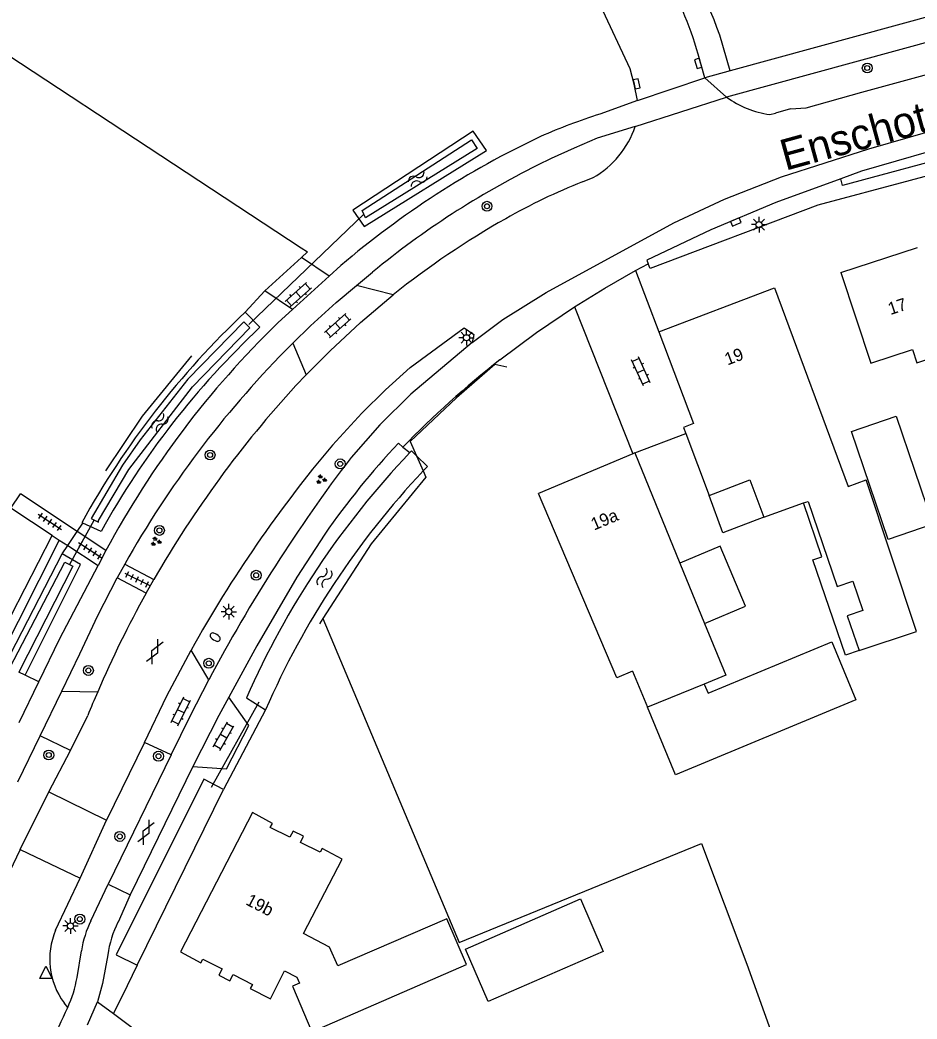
# Model space of a CAD drawing. Extents: x 136000 to 138005, y 398500 to 400500.
# Drawn here: x 137265.3 to 137337.6, y 398725.5 to 398806.1 of the extents above; entities that cross this region are included whole.
import ezdxf

# ---------------------------------------------------------------- set-up
doc = ezdxf.new("R2010")
doc.units = 0
for name, color, linetype in [('gg-afsc-erfafscheiding', 7, 'Continuous'), ('gg-afsc-hekwerk', 7, 'Continuous'), ('gg-anno-huisnummerreeks BGT', 7, 'Continuous'), ('gg-anno-openbare ruimte label', 7, 'Continuous'), ('gg-bbg-bijgebouw', 7, 'Continuous'), ('gg-bbg-gedigitaliseerde bebouwing', 7, 'Continuous'), ('gg-bbg-gedigitaliseerde bijgebouw', 7, 'Continuous'), ('gg-bbg-hoofdgebouw', 7, 'Continuous'), ('gg-bbg-luifel en loopbrug', 7, 'Continuous'), ('gg-bbg-tussenscheiding', 7, 'Continuous'), ('gg-knt-verharding', 7, 'Continuous'), ('gg-knt-verharding nz', 7, 'Continuous'), ('gg-kntw-bovenkant insteek waterloop', 7, 'Continuous'), ('gg-kntw-waterlijn', 7, 'Continuous'), ('gg-kwrk-duiker nz buis', 7, 'Continuous'), ('gt-grn-groengrens', 7, 'Continuous'), ('gt-grn-vlakafsluiter', 7, 'Continuous'), ('gt-grn-weggrens', 7, 'Continuous'), ('gt-grn-weggrens revisie', 7, 'Continuous'), ('gt-symb-boom', 7, 'Continuous'), ('gt-symb-brandkraan', 7, 'Continuous'), ('gt-symb-gesloten verharding', 7, 'Continuous'), ('gt-symb-groenvak', 7, 'Continuous'), ('gt-symb-klinker verharding', 7, 'Continuous'), ('gt-symb-kolk', 7, 'Continuous'), ('gt-symb-lichtmast', 7, 'Continuous'), ('gt-symb-tegel verharding', 7, 'Continuous'), ('gt-symb-waterafsluiter', 7, 'Continuous'), ('gt-symb-watersymbool', 7, 'Continuous')]:
    doc.layers.add(name, color=color, linetype=linetype)

# ---------------------------------------------------------------- blocks, each defined once
blk = doc.blocks.new('gt0-KOLK')
at = {"layer": 'gt-symb-kolk'}
blk.add_lwpolyline([(0, 0), (0.375, 0), (0.375, 0.4), (-0.375, 0.4), (-0.375, 0), (0, 0)], dxfattribs=at)
blk = doc.blocks.new('gt0-BOOM')
at = {"layer": 'gt-symb-boom'}
for radius in [0.4, 0.2]:
    blk.add_circle((0, 0), radius, dxfattribs=at)
blk = doc.blocks.new('gt0-LMAST')
at = {"layer": 'gt-symb-lichtmast'}
for p, q in [((-0.182, 0.173), (-0.447, 0.438)), ((-0.005, 0.246), (-0.005, 0.621)), ((0.172, 0.173), (0.437, 0.438)), ((-0.255, -0.004), (-0.63, -0.004)), ((-0.182, -0.181), (-0.447, -0.446)), ((-0.005, -0.254), (-0.005, -0.629)), ((0.437, -0.446), (0.172, -0.181)), ((0.245, -0.004), (0.62, -0.004))]:
    blk.add_line(p, q, dxfattribs=at)
blk.add_circle((-0.005, -0.004), 0.25, dxfattribs=at)
blk = doc.blocks.new('gt0-WA')
at = {"layer": 'gt-symb-watersymbool'}
for centre, start, end in [((-0.323, 0.022), 28.07249, 151.92751), ((0.427, 0.422), 208.07248, 331.92751), ((-0.323, -0.428), 28.07249, 151.92751), ((0.427, -0.028), 208.07248, 331.92751)]:
    blk.add_arc(centre, 0.425, start, end, dxfattribs=at)
blk = doc.blocks.new('gt0-KL1')
at = {"layer": 'gt-symb-klinker verharding'}
for p, q in [((-1.15, 0.3), (1.15, 0.3)), ((-1, -0.3), (-1, 0.3)), ((-0.5, 0.3), (-0.5, 0.45)), ((0, -0.3), (0, 0.3)), ((0.5, 0.3), (0.5, 0.45)), ((1, -0.3), (1, 0.3)), ((-1.15, -0.3), (1.15, -0.3)), ((-0.5, -0.45), (-0.5, -0.3)), ((0.5, -0.45), (0.5, -0.3))]:
    blk.add_line(p, q, dxfattribs=at)
blk = doc.blocks.new('gt0-GRVAK')
at = {"layer": 'gt-symb-groenvak'}
for p, q in [((-0.11, 0.189), (-0.228, 0.24)), ((-0.182, 0.153), (0.088, 0.153)), ((-0.091, 0.211), (-0.156, 0.322)), ((-0.047, 0.214), (-0.047, 0.393)), ((-0.004, 0.211), (0.061, 0.322)), ((0.015, 0.189), (0.133, 0.24)), ((0.262, -0.052), (0.197, 0.059)), ((0.305, -0.049), (0.305, 0.13)), ((0.349, -0.052), (0.414, 0.059)), ((-0.245, -0.228), (-0.363, -0.177)), ((-0.318, -0.264), (-0.047, -0.264)), ((-0.226, -0.206), (-0.291, -0.095)), ((-0.183, -0.203), (-0.183, -0.024)), ((-0.139, -0.206), (-0.074, -0.095)), ((-0.12, -0.228), (-0.002, -0.177)), ((0.243, -0.074), (0.125, -0.023)), ((0.17, -0.11), (0.441, -0.11)), ((0.368, -0.074), (0.486, -0.023))]:
    blk.add_line(p, q, dxfattribs=at)
blk = doc.blocks.new('gt0-TEG1')
at = {"layer": 'gt-symb-tegel verharding'}
for p, q in [((-1.125, 0), (1.125, 0)), ((-0.9, -0.25), (-0.9, 0.25)), ((-0.45, -0.25), (-0.45, 0.25)), ((0, -0.25), (0, 0.25)), ((0.45, -0.25), (0.45, 0.25)), ((0.9, -0.25), (0.9, 0.25))]:
    blk.add_line(p, q, dxfattribs=at)
blk = doc.blocks.new('gt0-GESVH1')
at = {"layer": 'gt-symb-gesloten verharding'}
for p, q in [((-0.992, -0.261), (0.008, 0.239)), ((0.008, -0.261), (-0.992, 0.239)), ((0.008, 0.239), (1.008, -0.261)), ((1.008, 0.239), (0.008, -0.261))]:
    blk.add_line(p, q, dxfattribs=at)
blk = doc.blocks.new('gt0-BR')
at = {"layer": 'gt-symb-brandkraan'}
for centre, radius, start, end in [((-0.244, 0), 0.206, 107.56694, 252.43307), ((0.599, -2.664), 3, 106.89205, 107.56694), ((0, -0.691), 0.938, 73.10799, 106.89205), ((-0.599, -2.664), 3, 72.43309, 73.10799), ((0.244, 0), 0.206, 287.56695, 72.43309), ((0.599, 2.664), 3, 252.43307, 253.10797), ((0, 0.691), 0.938, 253.10797, 286.89206), ((-0.599, 2.664), 3, 286.89206, 287.56695)]:
    blk.add_arc(centre, radius, start, end, dxfattribs=at)
blk = doc.blocks.new('gt0-WAFSL')
at = {"layer": 'gt-symb-waterafsluiter'}
for p, q in [((-0.5, -0.333), (0, 0.667)), ((0, 0.667), (0.5, -0.333)), ((0.5, -0.333), (-0.5, -0.333))]:
    blk.add_line(p, q, dxfattribs=at)

msp = doc.modelspace()

# ---------------------------------------------------------------- linework, layer by layer
at = {"layer": 'gg-afsc-erfafscheiding'}
for p, q in [((137296.169, 398771.652), (137296.732, 398771.214)), ((137297.28, 398770.944), (137297.812, 398769.736)), ((137269.922, 398764.848), (137270.373, 398765.518)), ((137268.48, 398764.154), (137263.489, 398754.349)), ((137269.158, 398763.714), (137269.922, 398764.848)), ((137268.709, 398763.046), (137269.158, 398763.714)), ((137289.729, 398757.837), (137289.448, 398757.402)), ((137285.102, 398750.459), (137281.717, 398744.031))]:
    msp.add_line(p, q, dxfattribs=at)
for points in [[(137250.72, 398812.364), (137252.997, 398810.764), (137287.97, 398787.727)], [(137250.72, 398812.364), (137252.997, 398810.764), (137287.97, 398787.727)], [(137272.223, 398769.732), (137275.178, 398774.158), (137279.169, 398779.016)], [(137304.558, 398778.093), (137303.594, 398778.308), (137300.506, 398775.632), (137296.765, 398772.114), (137297.28, 398770.944)], [(137297.812, 398769.736), (137298.037, 398769.226), (137293.624, 398763.868), (137289.729, 398757.837)]]:
    msp.add_lwpolyline(points, dxfattribs=at)
at = {"layer": 'gg-afsc-hekwerk'}
msp.add_line((137267.897, 398764.532), (137264.585, 398766.733), dxfattribs=at)
msp.add_line((137267.897, 398764.532), (137264.585, 398766.733), dxfattribs=at)
msp.add_lwpolyline([(137257.879, 398762.385), (137264.592, 398758.07), (137267.897, 398764.532)], dxfattribs=at)
msp.add_lwpolyline([(137257.879, 398762.385), (137264.592, 398758.07), (137267.897, 398764.532)], dxfattribs=at)
at = {"layer": 'gg-bbg-bijgebouw'}
msp.add_lwpolyline([(137310.487, 398735.226), (137312.31, 398730.976), (137303.054, 398726.952), (137301.22, 398731.17), (137310.487, 398735.226)], dxfattribs=at)
at = {"layer": 'gg-bbg-gedigitaliseerde bebouwing'}
for p, q in [((137318.977, 398772.766), (137320.878, 398767.766)), ((137314.861, 398771.185), (137318.508, 398762.303)), ((137325.284, 398766), (137328.459, 398767.151)), ((137318.508, 398762.303), (137320.499, 398757.433)), ((137314.679, 398753.575), (137315.883, 398750.675))]:
    msp.add_line(p, q, dxfattribs=at)
for points in [[(137331.49, 398785.73), (137333.891, 398778.42), (137337.252, 398779.525), (137337.604, 398778.455), (137340.358, 398779.36)], [(137326.14, 398784.49), (137332.063, 398768.473), (137333.51, 398769.008)], [(137316.8, 398780.94), (137319.606, 398773.558), (137318.794, 398773.249), (137318.977, 398772.766)], [(137320.878, 398767.766), (137324.141, 398769.006), (137325.284, 398766)], [(137332.944, 398755.261), (137337.574, 398756.782), (137333.51, 398769.008)], [(137314.679, 398753.575), (137313.41, 398753.037), (137307.107, 398767.914)], [(137328.459, 398767.151), (137328.84, 398767.281), (137331.181, 398760.427), (137332.443, 398760.858), (137333.251, 398758.489), (137331.989, 398758.058), (137332.944, 398755.261)], [(137320.499, 398757.433), (137322.206, 398753.26), (137320.463, 398752.547)]]:
    msp.add_lwpolyline(points, dxfattribs=at)
at = {"layer": 'gg-bbg-gedigitaliseerde bijgebouw'}
for points in [[(137335.946, 398774.146), (137338.905, 398765.435), (137335.307, 398764.213), (137332.348, 398772.924), (137335.946, 398774.146)], [(137320.463, 398752.547), (137320.772, 398751.803), (137330.751, 398755.946), (137332.692, 398751.271), (137318.144, 398745.23), (137315.883, 398750.675)]]:
    msp.add_lwpolyline(points, dxfattribs=at)
at = {"layer": 'gg-bbg-hoofdgebouw'}
for p, q in [((137331.49, 398785.73), (137337.665, 398787.76)), ((137316.8, 398780.94), (137326.14, 398784.49)), ((137314.719, 398771.125), (137307.107, 398767.914)), ((137314.861, 398771.185), (137314.719, 398771.125))]:
    msp.add_line(p, q, dxfattribs=at)
msp.add_lwpolyline([(137278.249, 398730.941), (137279.878, 398730.056), (137280.05, 398730.372), (137281.602, 398729.577), (137281.344, 398729.08), (137282.229, 398728.62), (137282.488, 398729.112), (137284.041, 398728.306), (137283.874, 398727.985), (137285.506, 398727.175), (137286.622, 398729.423), (137287.626, 398728.896), (137287.838, 398728.431), (137287.268, 398728.187), (137288.848, 398724.505), (137301.306, 398729.94), (137299.725, 398733.614), (137290.927, 398729.818), (137290.274, 398731.333), (137288.178, 398732.419), (137291.288, 398738.419), (137289.673, 398739.297), (137289.501, 398738.981), (137287.923, 398739.773), (137288.174, 398740.273), (137287.326, 398740.695), (137287.075, 398740.195), (137285.491, 398740.992), (137285.664, 398741.308), (137284.058, 398742.187), (137278.249, 398730.941)], dxfattribs=at)
at = {"layer": 'gg-bbg-luifel en loopbrug'}
for points in [[(137325.284, 398766), (137321.963, 398764.735), (137320.878, 398767.766)], [(137332.944, 398755.261), (137331.851, 398754.888), (137329.228, 398762.568), (137329.94, 398762.811), (137328.459, 398767.151)], [(137320.499, 398757.433), (137323.798, 398758.831), (137321.745, 398763.675), (137318.508, 398762.303)]]:
    msp.add_lwpolyline(points, dxfattribs=at)
at = {"layer": 'gg-bbg-tussenscheiding'}
msp.add_line((137320.463, 398752.547), (137315.883, 398750.675), dxfattribs=at)
at = {"layer": 'gg-knt-verharding'}
for p, q in [((137366.23, 398813.982), (137322.569, 398802.008)), ((137322.569, 398802.008), (137321.718, 398804.882)), ((137341.022, 398805.025), (137322.273, 398799.891)), ((137320.52, 398801.446), (137319.969, 398803.334)), ((137322.569, 398802.008), (137320.52, 398801.446)), ((137315.099, 398799.604), (137320.52, 398801.446)), ((137315.099, 398799.604), (137312.063, 398798.52)), ((137327.419, 398798.928), (137326.222, 398798.581)), ((137327.419, 398798.928), (137328.692, 398799.02)), ((137325.756, 398798.479), (137326.222, 398798.581)), ((137314.912, 398797.523), (137311.849, 398796.567)), ((137310.665, 398793.052), (137311.509, 398793.387)), ((137290.233, 398785.453), (137287.997, 398786.953)), ((137291.17, 398786.29), (137290.233, 398785.453)), ((137314.93, 398785.889), (137315.961, 398786.441)), ((137314.93, 398785.889), (137316.8, 398780.94)), ((137287.273, 398782.75), (137290.233, 398785.453)), ((137292.43, 398784.687), (137293.735, 398785.774)), ((137295.401, 398783.945), (137292.43, 398784.687)), ((137287.273, 398782.75), (137285.041, 398784.249)), ((137310.02, 398782.978), (137314.719, 398771.125)), ((137286.728, 398779.463), (137287.317, 398780.042)), ((137287.317, 398780.042), (137288.378, 398777.497)), ((137301.761, 398780.103), (137296.817, 398775.917)), ((137288.378, 398777.497), (137287.545, 398776.612)), ((137296.169, 398771.652), (137295.813, 398771.975)), ((137269.922, 398764.848), (137265.344, 398767.88)), ((137267.897, 398764.532), (137268.48, 398764.154)), ((137268.48, 398764.154), (137269.158, 398763.714)), ((137272.239, 398763.313), (137269.922, 398764.848)), ((137269.158, 398763.714), (137271.614, 398762.121)), ((137272.239, 398763.313), (137271.614, 398762.121)), ((137273.751, 398762.214), (137273.146, 398761.119)), ((137273.751, 398762.214), (137276.102, 398760.972)), ((137275.478, 398759.869), (137273.146, 398761.119)), ((137275.478, 398759.869), (137276.102, 398760.972)), ((137280.525, 398752.877), (137279.098, 398755.273)), ((137265.719, 398753.275), (137265.223, 398753.514)), ((137266.834, 398752.738), (137265.719, 398753.275)), ((137265.254, 398749.457), (137266.834, 398752.738)), ((137266.948, 398748.374), (137268.685, 398751.975)), ((137268.685, 398751.975), (137271.575, 398751.927)), ((137269.396, 398747.18), (137270.771, 398750)), ((137265.151, 398744.65), (137266.948, 398748.374)), ((137269.396, 398747.18), (137266.948, 398748.374)), ((137275.336, 398747.846), (137272.283, 398741.581)), ((137277.502, 398746.852), (137275.336, 398747.846)), ((137267.633, 398743.847), (137269.396, 398747.18)), ((137277.502, 398746.852), (137272.419, 398736.42)), ((137279.255, 398745.911), (137274.19, 398735.555)), ((137265.33, 398739.199), (137267.633, 398743.847)), ((137270.172, 398736.887), (137272.283, 398741.581)), ((137265.33, 398739.199), (137270.172, 398736.887)), ((137268.181, 398732.694), (137270.172, 398736.887)), ((137271.03, 398733.455), (137272.419, 398736.42)), ((137274.19, 398735.555), (137273.212, 398733.346)), ((137269.912, 398728.869), (137270.261, 398731.046)), ((137269.161, 398726.471), (137268.86, 398726.839)), ((137270.763, 398725.078), (137271.547, 398726.915)), ((137271.547, 398726.915), (137272.856, 398725.98))]:
    msp.add_line(p, q, dxfattribs=at)
for points in [[(137315.099, 398799.604), (137314.825, 398800.914), (137314.506, 398802.174), (137312.103, 398807.279), (137309.707, 398810.596), (137296.165, 398824.608)], [(137328.692, 398799.02), (137333.18, 398800.28), (137341.732, 398802.626)], [(137359.39, 398799.13), (137329.63, 398791.17), (137316.12, 398786.05), (137315.961, 398786.441)], [(137311.849, 398796.567), (137309.981, 398795.775), (137308.134, 398794.928), (137307.034, 398794.392)], [(137341.351, 398796.282), (137341.595, 398795.45), (137331.605, 398792.765), (137331.482, 398793.303)], [(137341.351, 398796.282), (137333.15, 398793.91), (137331.482, 398793.303)], [(137331.482, 398793.303), (137326.23, 398791.39), (137321.01, 398789.19), (137315.84, 398786.74), (137315.961, 398786.441)], [(137310.02, 398782.978), (137312.449, 398784.478), (137314.93, 398785.889)], [(137287.317, 398780.042), (137288.73, 398781.431), (137290.8, 398783.33), (137292.43, 398784.687)], [(137288.378, 398777.497), (137290.31, 398779.42), (137292.756, 398781.704), (137295.401, 398783.945)], [(137286.095, 398781.671), (137286.125, 398781.7), (137287.273, 398782.75)], [(137303.997, 398778.691), (137306.958, 398780.905), (137310.02, 398782.978)], [(137296.774, 398778.07), (137301.127, 398781.268), (137301.908, 398780.738), (137301.761, 398780.103)], [(137290.5, 398771.82), (137292.874, 398774.384), (137294.787, 398776.27), (137296.774, 398778.07)], [(137296.817, 398775.917), (137294.31, 398773.45), (137291.996, 398770.825)], [(137289.873, 398764.645), (137287.63, 398761.16), (137284.396, 398755.628), (137282.146, 398751.494)], [(137266.834, 398752.738), (137268.51, 398756.22), (137271.614, 398762.121)], [(137268.685, 398751.975), (137270.143, 398754.996), (137271.581, 398758.089), (137273.146, 398761.119)], [(137275.336, 398747.846), (137277.144, 398751.597), (137279.098, 398755.273)], [(137277.502, 398746.852), (137279.043, 398750), (137280.525, 398752.877)], [(137279.255, 398745.911), (137281.959, 398745.7), (137283.752, 398749.202), (137282.146, 398751.494)], [(137282.146, 398751.494), (137281.333, 398750), (137279.255, 398745.911)], [(137265.33, 398739.199), (137261.891, 398732.041), (137260.975, 398730.257)], [(137272.392, 398730.711), (137271.965, 398728.403), (137271.547, 398726.915)], [(137272.856, 398725.98), (137274.252, 398724.918), (137275.515, 398723.902), (137276.124, 398723.348), (137277.041, 398722.384), (137277.641, 398721.621), (137278.238, 398720.742), (137278.793, 398719.845), (137279.845, 398717.969), (137297.552, 398678.001)]]:
    msp.add_lwpolyline(points, dxfattribs=at)
for centre, radius, start, end in [((137294.077, 398796.208), 26.855, 15.3876, 47.09838), ((137290.744, 398794.088), 32.801, 19.21251, 37.71356), ((137326.736, 398805.899), 7.485, 233.39182, 262.47314), ((137326.664, 398752.756), 48.037, 107.69522, 113.81688), ((137307.695, 398799.993), 7.628, 300.00114, 341.10543), ((137338.134, 398731.335), 72.289, 115.27811, 130.51702), ((137338.372, 398731.462), 70.301, 116.47245, 129.41553), ((137328.34, 398748.314), 48.103, 111.55833, 119.76211), ((137338.822, 398729.495), 69.643, 119.56228, 128.57042), ((137338.141, 398727.98), 74.776, 134.10894, 151.80251), ((137345.128, 398722.021), 81.916, 135.4737, 150.61556), ((137352.45, 398716.934), 78.496, 128.11718, 135.80708), ((137352.445, 398717.122), 88.04, 137.49026, 150.12763), ((137371.215, 398704), 105.426, 139.96171, 150.89936), ((137344.948, 398726.086), 67.231, 136.95629, 145.00328), ((137397.115, 398691.001), 131.991, 142.78819, 152.04456), ((137352.685, 398716.997), 88.312, 150.9569, 156.70059), ((137351.413, 398717.485), 86.951, 156.66474, 158.04065), ((137278.467, 398729.754), 8.307, 153.54119, 171.0506), ((137280.627, 398729.593), 8.311, 153.15697, 172.27123), ((137273.686, 398730.366), 5.977, 157.0747, 216.1553), ((137260.285, 398730.568), 9.776, 335.22659, 349.99463), ((137221.112, 398747.638), 52.505, 328.9335, 336.22483)]:
    msp.add_arc(centre, radius, start, end, dxfattribs=at)
at = {"layer": 'gg-knt-verharding nz'}
msp.add_line((137314.912, 398797.523), (137322.273, 398799.891), dxfattribs=at)
msp.add_lwpolyline([(137301.761, 398780.103), (137304.227, 398781.942), (137307.739, 398784.112), (137318.029, 398789.738), (137322.103, 398791.66), (137326.699, 398793.453), (137333.724, 398795.713), (137347.165, 398799.586), (137354.274, 398801.454)], dxfattribs=at)
at = {"layer": 'gg-kntw-bovenkant insteek waterloop'}
for p, q in [((137283.465, 398782.534), (137284.654, 398781.319)), ((137270.289, 398765.555), (137270.373, 398765.518)), ((137271.848, 398764.861), (137270.373, 398765.518)), ((137264.081, 398754.064), (137268.709, 398763.046)), ((137283.565, 398751.437), (137285.102, 398750.459)), ((137280.133, 398744.889), (137273.062, 398730.711)), ((137281.717, 398744.031), (137280.133, 398744.889)), ((137274.757, 398729.877), (137281.717, 398744.031)), ((137273.062, 398730.711), (137274.757, 398729.877))]:
    msp.add_line(p, q, dxfattribs=at)
for points in [[(137302.921, 398795.59), (137301.841, 398797.136), (137292.144, 398790.757)], [(137292.144, 398790.757), (137293.057, 398789.459), (137302.921, 398795.59)], [(137297.28, 398770.944), (137296.859, 398771.347), (137296.732, 398771.214)], [(137297.28, 398770.944), (137298.16, 398770.103), (137297.812, 398769.736)], [(137265.719, 398753.275), (137270.201, 398762.2), (137268.709, 398763.046)]]:
    msp.add_lwpolyline(points, dxfattribs=at)
for centre, radius, start, end in [((137331.133, 398731.941), 69.512, 133.29496, 151.08087), ((137331.164, 398731.918), 67.85, 133.27366, 150.95324), ((137346.795, 398723.612), 69.081, 136.44325, 156.24751), ((137346.873, 398723.56), 67.374, 136.73496, 156.46852)]:
    msp.add_arc(centre, radius, start, end, dxfattribs=at)
at = {"layer": 'gg-kntw-waterlijn'}
for points in [[(137292.901, 398790.74), (137301.709, 398796.434), (137302.156, 398795.744), (137293.175, 398790.147), (137292.901, 398790.74)], [(137271.642, 398765.61), (137271.642, 398765.725), (137274.092, 398769.859), (137279.215, 398776.53), (137283.843, 398781.287), (137283.349, 398781.768), (137278.832, 398777.125), (137275.001, 398772.234), (137273.585, 398770.204), (137271.043, 398765.91), (137271.642, 398765.61)], [(137264.499, 398753.863), (137268.92, 398762.379), (137269.559, 398762.047), (137265.223, 398753.514)]]:
    msp.add_lwpolyline(points, dxfattribs=at)
at = {"layer": 'gg-kwrk-duiker nz buis'}
for p, q in [((137293.038, 398790.444), (137283.765, 398781.556)), ((137269.327, 398762.205), (137271.302, 398765.774)), ((137284.562, 398751.078), (137280.722, 398744.203))]:
    msp.add_line(p, q, dxfattribs=at)
at = {"layer": 'gt-grn-groengrens'}
for p, q in [((137274.757, 398729.877), (137273.938, 398728.212)), ((137273.938, 398728.212), (137272.856, 398725.98))]:
    msp.add_line(p, q, dxfattribs=at)
at = {"layer": 'gt-grn-vlakafsluiter'}
for p, q in [((137287.97, 398787.727), (137288.478, 398787.393)), ((137285.041, 398784.249), (137287.997, 398786.953)), ((137287.997, 398786.953), (137288.478, 398787.393)), ((137283.465, 398782.534), (137285.041, 398784.249)), ((137314.861, 398771.185), (137318.977, 398772.766)), ((137264.585, 398766.733), (137265.344, 398767.88))]:
    msp.add_line(p, q, dxfattribs=at)
msp.add_lwpolyline([(137289.729, 398757.837), (137300.715, 398731.71), (137320.24, 398739.687), (137323.898, 398729.97), (137327.059, 398721.108), (137341.614, 398677.799), (137352.958, 398643.758), (137373.41, 398649.223), (137374.591, 398645.681)], dxfattribs=at)
at = {"layer": 'gt-grn-weggrens'}
msp.add_line((137320.52, 398801.446), (137322.273, 398799.891), dxfattribs=at)
at = {"layer": 'gt-grn-weggrens revisie'}
for p, q in [((137267.633, 398743.847), (137272.283, 398741.581)), ((137272.419, 398736.42), (137274.19, 398735.555))]:
    msp.add_line(p, q, dxfattribs=at)

# ---------------------------------------------------------------- block references
at = {"layer": 'gt-symb-boom'}
for p in [(137333.61, 398802.228), (137302.955, 398791.078), (137280.635, 398771.021), (137291.123, 398770.305), (137276.55, 398764.94), (137284.349, 398761.321), (137280.532, 398754.222), (137270.824, 398753.644), (137267.634, 398746.824), (137276.476, 398746.729), (137273.357, 398740.257), (137270.135, 398733.59)]:
    msp.add_blockref('gt0-BOOM', p, dxfattribs=at)
at = {"layer": 'gt-symb-brandkraan', "rotation": 146.75506275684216}
msp.add_blockref('gt0-BR', (137281.048, 398756.329), dxfattribs=at)
at = {"layer": 'gt-symb-gesloten verharding', "rotation": 63.76806006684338}
for p in [(137276.163, 398755.151), (137275.46, 398740.597)]:
    msp.add_blockref('gt0-GESVH1', p, dxfattribs=at)
at = {"layer": 'gt-symb-groenvak'}
for p in [(137289.583, 398769.044), (137276.253, 398764.037)]:
    msp.add_blockref('gt0-GRVAK', p, dxfattribs=at)
at = {"layer": 'gt-symb-klinker verharding'}
for p, rotation in [((137287.744, 398783.951), 41.83814925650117), ((137290.921, 398781.451), 41.83814925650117), ((137315.361, 398777.767), 114.51507073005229), ((137278.275, 398750.348), 63.76806006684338), ((137281.723, 398748.341), 60.25511870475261)]:
    msp.add_blockref('gt0-KL1', p, dxfattribs=dict(at, rotation=rotation))
at = {"layer": 'gt-symb-kolk'}
for p, rotation in [((137320.171, 398802.65), 106.4874537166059), ((137314.825, 398800.914), -78.1994521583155), ((137323.089, 398789.632), 22.822540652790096)]:
    msp.add_blockref('gt0-KOLK', p, dxfattribs=dict(at, rotation=rotation))
at = {"layer": 'gt-symb-lichtmast'}
for p in [(137324.895, 398789.604), (137301.311, 398780.478), (137282.148, 398758.383), (137269.386, 398733.04)]:
    msp.add_blockref('gt0-LMAST', p, dxfattribs=at)
at = {"layer": 'gt-symb-tegel verharding'}
for p, rotation in [((137267.728, 398765.627), -33.29284857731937), ((137270.963, 398763.334), -33.24493724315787), ((137274.765, 398760.997), -26.565051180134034)]:
    msp.add_blockref('gt0-TEG1', p, dxfattribs=dict(at, rotation=rotation))
at = {"layer": 'gt-symb-waterafsluiter'}
msp.add_blockref('gt0-WAFSL', (137267.398, 398729.125), dxfattribs=at)
at = {"layer": 'gt-symb-watersymbool'}
for p, rotation in [((137297.321, 398793.233), 31.877816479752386), ((137276.56, 398773.601), 52.43140797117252), ((137289.832, 398761.066), 63.76806006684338)]:
    msp.add_blockref('gt0-WA', p, dxfattribs=dict(at, rotation=rotation))

# ---------------------------------------------------------------- texts
at = {"layer": 'gg-anno-huisnummerreeks BGT'}
for s, rotation, p in [('17', 18.2, (137335.472, 398782.302)), ('19', 20.8, (137322.342, 398778.233)), ('19a', 22.9, (137311.588, 398764.92)), ('19b', 332.7, (137283.432, 398734.802))]:
    msp.add_text(s, height=1, rotation=rotation, dxfattribs=at).set_placement(p)
at = {"layer": 'gg-anno-openbare ruimte label'}
msp.add_text('Enschotsebaan', height=2.5, rotation=15.4, dxfattribs=at).set_placement((137327.008, 398793.935))

doc.saveas('drawing.dxf')
